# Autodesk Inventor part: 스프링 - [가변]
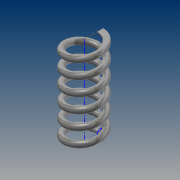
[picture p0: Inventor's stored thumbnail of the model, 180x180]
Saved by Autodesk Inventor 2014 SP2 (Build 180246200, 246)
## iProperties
Created: 2015-12
Part Number: 스프링 - [가변]
Material: 강철, 탄소
Document SubType Name: Modeling
Designer: Administrator
Mass: 16.5345 g
Surface Area: 28.5107 cm^2
Volume: 2.10095 cm^3
Density: 7.87 g/cm^3
Appearance: 반연마
Author: Administrator
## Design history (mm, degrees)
sketch "스케치2"
  geometry: L1 (0, 0)-(8, 0); L2 (8, 0)-(8, 42); L3 (8, 42)-(0, 42); L4 (0, 42)-(0, 0); C1 r 1.5 at (8, 0)
  constraints: 8 end point, 2 parallel, 1 centre point, 1 coincident, 1 horizontal, 1 perpendicular
  dimensions: "d2" = 16 diameter of L2 L4; "d3" = 42 distance of L1.end L2.end (derived); "d4" = 3 diameter of C1
feature "코일1" sketch "스케치2" pitch "d5" = 10; turns "d7" = 6; dims "d6" = 42 (= d3), "d8" = 0, angle "d9" = 90 deg, angle "d10" = 90 deg, "d11" = 0, "d12" = 0
node "작업 평면1"
feature "분할1"
feature "분할2"
node "솔리드1"
other parameters: "d13" = 0
